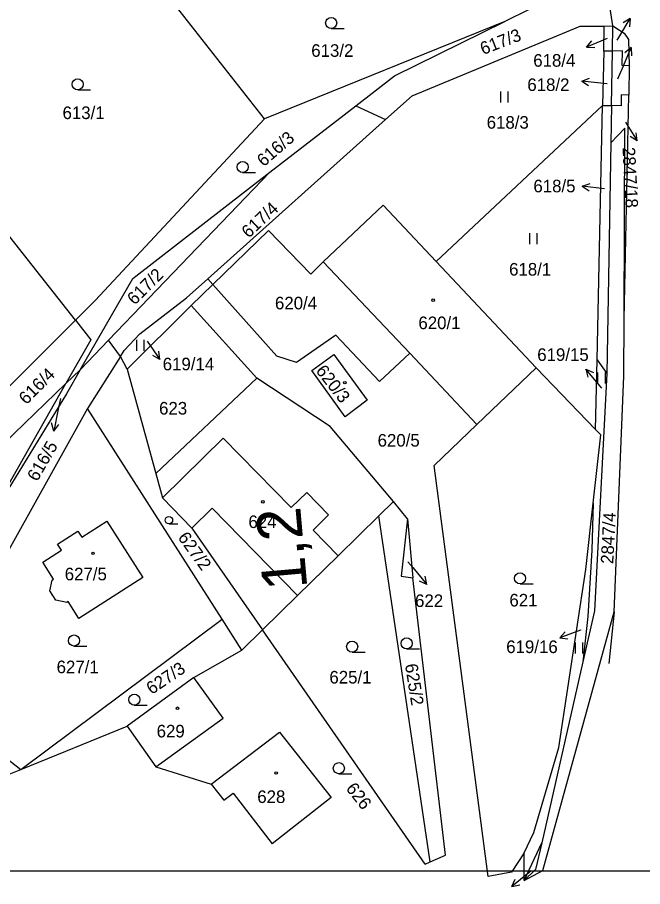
# Model space of a CAD drawing. Extents: x -558358 to -557517, y -1073786 to -1073189.
# Drawn here: x -558268.9 to -558184.5, y -1073786.2 to -1073668.8 of the extents above; entities that cross this region are included whole.
import ezdxf

# ---------------------------------------------------------------- set-up
doc = ezdxf.new("R2010")
doc.units = 0
for name, color, linetype in [('Hranice parcel', 7, 'Continuous'), ('Návěst místo trati', 7, 'Continuous'), ('Parcelní čísla', 7, 'Continuous'), ('Pop  PČ popisy', 7, 'Continuous'), ('Vnitřní kresba', 7, 'Continuous'), ('Vrstva 1', 7, 'Continuous'), ('Značky budov', 7, 'Continuous'), ('Značky kultur', 7, 'Continuous')]:
    doc.layers.add(name, color=color, linetype=linetype)

msp = doc.modelspace()

# ---------------------------------------------------------------- linework, layer by layer
at = {"layer": 'Hranice parcel'}
for p, q in [((-558235.56, -1073682.51), (-558250.61, -1073663.38)), ((-558188.53, -1073669.97), (-558189.35, -1073664.58)), ((-558196.23, -1073665.95), (-558203.14, -1073669.36)), ((-558203.14, -1073669.36), (-558235.56, -1073682.51)), ((-558189.77, -1073673.37), (-558189.69, -1073669.98)), ((-558189.69, -1073669.98), (-558188.53, -1073669.97)), ((-558188.59, -1073673.36), (-558188.53, -1073669.97)), ((-558188.53, -1073669.97), (-558186.98, -1073670.93)), ((-558189.77, -1073673.37), (-558189.93, -1073680.69)), ((-558188.59, -1073673.36), (-558189.77, -1073673.37)), ((-558188.72, -1073680.72), (-558188.59, -1073673.36)), ((-558187.23, -1073673.34), (-558188.59, -1073673.36)), ((-558186.31, -1073675.34), (-558186.36, -1073679.31)), ((-558261.12, -1073709.7), (-558287.25, -1073676.53)), ((-558187.01, -1073709.55), (-558186.36, -1073679.31)), ((-558234.84, -1073689.73), (-558223.26, -1073680.77)), ((-558223.26, -1073680.77), (-558219.23, -1073682.6)), ((-558189.93, -1073680.69), (-558212.4, -1073701.75)), ((-558190.64, -1073715.05), (-558189.93, -1073680.69)), ((-558189.93, -1073680.69), (-558188.72, -1073680.72)), ((-558188.72, -1073680.72), (-558188.81, -1073685.75)), ((-558187.4, -1073680.75), (-558188.72, -1073680.72)), ((-558243.24, -1073704.13), (-558219.23, -1073682.6)), ((-558186.92, -1073683.79), (-558188.81, -1073685.75)), ((-558187.01, -1073709.55), (-558186.92, -1073683.79)), ((-558188.81, -1073685.75), (-558189.35, -1073716.89)), ((-558256.63, -1073712.41), (-558234.84, -1073689.73)), ((-558227.63, -1073701.8), (-558215.96, -1073714.16)), ((-558212.4, -1073701.75), (-558198.87, -1073716.11)), ((-558245.46, -1073707.69), (-558242.57, -1073704.88)), ((-558242.57, -1073704.88), (-558243.24, -1073704.13)), ((-558233.91, -1073714.56), (-558242.57, -1073704.88)), ((-558245.46, -1073707.69), (-558254.11, -1073716.3)), ((-558236.6, -1073717.53), (-558245.46, -1073707.69)), ((-558256.63, -1073712.41), (-558260.45, -1073716.38)), ((-558255.01, -1073714.6), (-558256.63, -1073712.41)), ((-558206.91, -1073723.76), (-558215.96, -1073714.16)), ((-558255.01, -1073714.6), (-558259.48, -1073721.62)), ((-558254.11, -1073716.3), (-558255.01, -1073714.6)), ((-558190.86, -1073724.46), (-558190.64, -1073715.05)), ((-558190.64, -1073715.05), (-558189.35, -1073716.89)), ((-558262.39, -1073718.25), (-558260.45, -1073716.38)), ((-558254.11, -1073716.3), (-558250.26, -1073730.4)), ((-558198.87, -1073716.11), (-558206.91, -1073723.76)), ((-558190.86, -1073724.46), (-558198.87, -1073716.11)), ((-558250.26, -1073730.4), (-558236.6, -1073717.53)), ((-558226.69, -1073724.03), (-558236.6, -1073717.53)), ((-558274.72, -1073739.9), (-558262.39, -1073718.25)), ((-558259.48, -1073721.62), (-558281.15, -1073760.49)), ((-558241.29, -1073750.06), (-558259.48, -1073721.62)), ((-558218.17, -1073734.19), (-558226.69, -1073724.03)), ((-558250.26, -1073730.4), (-558249.36, -1073733.68)), ((-558220.12, -1073736.1), (-558218.17, -1073734.19)), ((-558216.24, -1073736.49), (-558218.17, -1073734.19)), ((-558191.18, -1073734.38), (-558191.35, -1073740.76)), ((-558213.21, -1073782.82), (-558220.12, -1073736.1)), ((-558216.24, -1073736.49), (-558215.54, -1073744.47)), ((-558191.35, -1073740.76), (-558191.89, -1073749.68)), ((-558191.89, -1073749.68), (-558192.59, -1073755.8)), ((-558188.37, -1073749.08), (-558189.08, -1073756.06)), ((-558268.5, -1073770.34), (-558241.29, -1073750.06)), ((-558238.63, -1073754.22), (-558241.29, -1073750.06)), ((-558235.84, -1073751.49), (-558238.63, -1073754.22)), ((-558213.89, -1073783.12), (-558235.84, -1073751.49)), ((-558245.1, -1073757.92), (-558238.63, -1073754.22)), ((-558192.59, -1073755.8), (-558198.14, -1073780.25)), ((-558245.1, -1073757.92), (-558254.1, -1073764.51)), ((-558281.15, -1073760.49), (-558268.5, -1073770.34)), ((-558268.5, -1073770.34), (-558254.1, -1073764.51)), ((-558254.1, -1073764.51), (-558250.25, -1073769.98)), ((-558279.1, -1073774.62), (-558268.5, -1073770.34)), ((-558250.25, -1073769.98), (-558242.76, -1073772.31)), ((-558200.51, -1073785.33), (-558198.14, -1073780.25)), ((-558200.51, -1073785.33), (-558200.5, -1073781.61)), ((-558213.89, -1073783.12), (-558213.21, -1073782.82))]:
    msp.add_line(p, q, dxfattribs=at)
for points in [[(-558223.26, -1073680.77), (-558218.03, -1073676.72), (-558203.14, -1073669.36)], [(-558219.23, -1073682.6), (-558215.65, -1073679.39), (-558192.95, -1073670.01), (-558189.69, -1073669.98)], [(-558186.98, -1073670.93), (-558186.43, -1073671.79), (-558186.31, -1073675.34)], [(-558186.31, -1073675.34), (-558187.29, -1073675.33), (-558187.23, -1073673.34)], [(-558186.36, -1073679.31), (-558187.4, -1073679.28), (-558187.4, -1073680.75)], [(-558235.56, -1073682.51), (-558258.46, -1073707.03), (-558261.12, -1073709.7)], [(-558260.45, -1073716.38), (-558253.37, -1073704.07), (-558234.84, -1073689.73)], [(-558227.63, -1073701.8), (-558219.54, -1073694.18), (-558212.4, -1073701.75)], [(-558242.57, -1073704.88), (-558235.04, -1073697.59), (-558229.33, -1073703.46), (-558227.63, -1073701.8)], [(-558255.01, -1073714.6), (-558254.51, -1073713.78), (-558252.39, -1073711.53), (-558246.1, -1073706.69), (-558243.24, -1073704.13)], [(-558289.37, -1073741.07), (-558281.4, -1073729.91), (-558261.12, -1073709.7)], [(-558261.12, -1073709.7), (-558259.03, -1073712.35), (-558262.39, -1073718.25)], [(-558188.37, -1073749.08), (-558187.04, -1073717.25), (-558187.01, -1073709.55)], [(-558215.96, -1073714.16), (-558220.05, -1073717.99), (-558225.94, -1073711.71), (-558231.23, -1073715.41), (-558233.91, -1073714.56)], [(-558224.7, -1073722.72), (-558229.2, -1073716.48), (-558226.19, -1073714.33), (-558221.69, -1073720.48), (-558224.7, -1073722.72)], [(-558260.45, -1073716.38), (-558262.32, -1073719.63), (-558274.72, -1073739.9)], [(-558189.35, -1073716.89), (-558191.03, -1073748.95), (-558192.59, -1073755.8)], [(-558262.39, -1073718.25), (-558277.79, -1073733.11), (-558288.61, -1073748.35)], [(-558200.5, -1073781.61), (-558202.2, -1073784.23), (-558205.35, -1073784.79), (-558212.68, -1073729.29), (-558206.91, -1073723.76)], [(-558191.18, -1073734.38), (-558190.17, -1073725.16), (-558190.86, -1073724.46)], [(-558249.36, -1073733.68), (-558245.38, -1073737.75), (-558235.84, -1073751.49)], [(-558200.5, -1073781.61), (-558199.18, -1073778.85), (-558195.83, -1073767.37), (-558192.17, -1073743.33), (-558191.18, -1073734.38)], [(-558235.84, -1073751.49), (-558231.13, -1073746.88), (-558225.62, -1073741.49), (-558220.12, -1073736.1)], [(-558216.24, -1073736.49), (-558217.14, -1073744.24), (-558215.54, -1073744.47)], [(-558264.25, -1073744.77), (-558264.05, -1073744.64), (-558265.49, -1073742.37), (-558262.97, -1073740.76), (-558263.51, -1073739.92), (-558260.77, -1073738.16), (-558260.22, -1073739), (-558256.85, -1073736.83), (-558251.99, -1073744.42), (-558260.65, -1073749.95), (-558262.08, -1073747.68), (-558262.29, -1073747.81), (-558263.76, -1073747.5), (-558264.56, -1073746.23), (-558264.25, -1073744.77)], [(-558213.21, -1073782.82), (-558211.14, -1073781.9), (-558215.54, -1073744.47)], [(-558200.51, -1073785.33), (-558197.97, -1073783.99), (-558188.37, -1073749.08)], [(-558250.25, -1073769.98), (-558241.14, -1073763.44), (-558245.1, -1073757.92)], [(-558242.76, -1073772.31), (-558233.55, -1073765.31), (-558226.57, -1073774.11), (-558234.56, -1073780.4)], [(-558242.76, -1073772.31), (-558241.08, -1073774.51), (-558239.8, -1073773.53), (-558234.56, -1073780.4)], [(-558198.14, -1073780.25), (-558198.96, -1073783.85), (-558200.51, -1073785.33)]]:
    msp.add_lwpolyline(points, dxfattribs=at)
at = {"layer": 'Pop  PČ popisy'}
for p, q in [((-558187.72, -1073671.53), (-558186.17, -1073668.96)), ((-558186.17, -1073668.96), (-558187.12, -1073669.56)), ((-558186.17, -1073668.96), (-558186.26, -1073670.07)), ((-558189.32, -1073671.65), (-558192.08, -1073672.82)), ((-558192.08, -1073672.82), (-558191.36, -1073671.97)), ((-558187.93, -1073671.89), (-558187.72, -1073671.53)), ((-558192.08, -1073672.82), (-558190.96, -1073672.89)), ((-558187.24, -1073675.66), (-558186.07, -1073672.9)), ((-558186.07, -1073672.9), (-558186.92, -1073673.62)), ((-558186.07, -1073672.9), (-558186, -1073674.02)), ((-558187.86, -1073677.09), (-558187.24, -1073675.66)), ((-558192.74, -1073677.42), (-558191.7, -1073677.02)), ((-558189.76, -1073677.73), (-558192.74, -1073677.42)), ((-558192.74, -1073677.42), (-558191.8, -1073678.02)), ((-558189.29, -1073677.78), (-558189.76, -1073677.73)), ((-558186.84, -1073682.95), (-558185.25, -1073685.5)), ((-558185.25, -1073685.5), (-558186.2, -1073684.91)), ((-558185.25, -1073685.5), (-558185.36, -1073684.38)), ((-558192.66, -1073691.6), (-558191.6, -1073691.23)), ((-558189.68, -1073691.97), (-558192.66, -1073691.6)), ((-558192.66, -1073691.6), (-558191.73, -1073692.22)), ((-558251.41, -1073712.52), (-558249.69, -1073714.98)), ((-558249.69, -1073714.98), (-558250.67, -1073714.45)), ((-558249.69, -1073714.98), (-558249.85, -1073713.87)), ((-558190.25, -1073718.6), (-558192.18, -1073716.3)), ((-558192.18, -1073716.3), (-558191.15, -1073716.75)), ((-558192.18, -1073716.3), (-558191.92, -1073717.39)), ((-558190.03, -1073718.86), (-558190.25, -1073718.6)), ((-558263.11, -1073720.25), (-558263.42, -1073721.72)), ((-558263.42, -1073721.72), (-558264.04, -1073724.66)), ((-558264.04, -1073724.66), (-558264.33, -1073723.57)), ((-558264.04, -1073724.66), (-558263.35, -1073723.78)), ((-558216.21, -1073742.3), (-558215.56, -1073743.06)), ((-558215.56, -1073743.06), (-558213.63, -1073745.36)), ((-558213.63, -1073745.36), (-558214.66, -1073744.91)), ((-558213.63, -1073745.36), (-558213.89, -1073744.27)), ((-558192.9, -1073751.52), (-558195.7, -1073752.59)), ((-558195.7, -1073752.59), (-558194.95, -1073751.77)), ((-558192.88, -1073751.51), (-558192.9, -1073751.52)), ((-558195.7, -1073752.59), (-558194.59, -1073752.7)), ((-558199.85, -1073784.27), (-558202.18, -1073786.16)), ((-558199.56, -1073784.03), (-558199.85, -1073784.27)), ((-558202.18, -1073786.16), (-558201.72, -1073785.14)), ((-558202.18, -1073786.16), (-558201.09, -1073785.92))]:
    msp.add_line(p, q, dxfattribs=at)
at = {"layer": 'Vnitřní kresba'}
for p, q in [((-558249.36, -1073733.68), (-558241.14, -1073725.64)), ((-558241.14, -1073725.64), (-558231.97, -1073735)), ((-558231.97, -1073735), (-558229.86, -1073732.94)), ((-558229.86, -1073732.94), (-558226.91, -1073735.96)), ((-558245.38, -1073737.75), (-558242.66, -1073735.09)), ((-558242.66, -1073735.09), (-558231.13, -1073746.88)), ((-558229.02, -1073738.02), (-558226.91, -1073735.96)), ((-558229.02, -1073738.02), (-558225.62, -1073741.49))]:
    msp.add_line(p, q, dxfattribs=at)
at = {"layer": 'Vrstva 1'}
msp.add_line((-557516.53, -1073784.09), (-558357.53, -1073784.09), dxfattribs=at)
at = {"layer": 'Značky budov'}
for centre in [(-558212.8, -1073706.99), (-558224.72, -1073718.13), (-558235.8, -1073734.21), (-558258.73, -1073741.17), (-558247.32, -1073762.08), (-558233.99, -1073770.82)]:
    msp.add_circle(centre, 0.175, dxfattribs=at)
at = {"layer": 'Značky kultur'}
for p, q in [((-558226.57, -1073670.32), (-558224.82, -1073670.32)), ((-558260.8, -1073678.6), (-558259.05, -1073678.6)), ((-558203.68, -1073680.3), (-558203.68, -1073678.8)), ((-558202.68, -1073680.3), (-558202.68, -1073678.8)), ((-558238.53, -1073689.76), (-558236.78, -1073689.76)), ((-558199.75, -1073699.45), (-558199.75, -1073697.95)), ((-558198.75, -1073699.45), (-558198.75, -1073697.95)), ((-558252.83, -1073713.85), (-558252.83, -1073712.35)), ((-558251.83, -1073713.85), (-558251.83, -1073712.35)), ((-558190.54, -1073718.24), (-558190.54, -1073716.74)), ((-558189.54, -1073718.24), (-558189.54, -1073716.74)), ((-558248.47, -1073737.19), (-558247.3, -1073737.19)), ((-558201.06, -1073745.3), (-558199.31, -1073745.3)), ((-558193.57, -1073754.69), (-558193.57, -1073753.19)), ((-558192.57, -1073754.69), (-558192.57, -1073753.19)), ((-558261.31, -1073753.69), (-558259.56, -1073753.69)), ((-558216.38, -1073754.08), (-558214.63, -1073754.08)), ((-558223.74, -1073754.51), (-558221.99, -1073754.51)), ((-558253.16, -1073761.67), (-558251.41, -1073761.67)), ((-558225.53, -1073770.92), (-558223.78, -1073770.92))]:
    msp.add_line(p, q, dxfattribs=at)
for centre, radius in [((-558226.57, -1073669.57), 0.75), ((-558260.8, -1073677.85), 0.75), ((-558238.53, -1073689.01), 0.75), ((-558248.48, -1073736.69), 0.502), ((-558201.06, -1073744.55), 0.75), ((-558261.3, -1073752.94), 0.75), ((-558223.74, -1073753.76), 0.75), ((-558216.38, -1073753.33), 0.75), ((-558253.16, -1073760.92), 0.75), ((-558225.53, -1073770.17), 0.75)]:
    msp.add_circle(centre, radius, dxfattribs=at)

# ---------------------------------------------------------------- texts
at = {"layer": 'Návěst místo trati'}
msp.add_text('1,2', height=6, rotation=95.054, dxfattribs=at).set_placement((-558229.78, -1073745.86))
at = {"layer": 'Parcelní čísla'}
for s, rotation, p in [('617/3', 21, (-558206.06, -1073673.9)), ('616/3', 41, (-558235.68, -1073689.06)), ('2847/18', 273, (-558187.23, -1073686.37)), ('617/4', 43, (-558237.71, -1073698.7)), ('617/2', 45, (-558253.11, -1073707.74)), ('616/4', 45, (-558267.74, -1073721.18)), ('620/3', 308, (-558228.73, -1073716.55)), ('616/5', 60, (-558266.27, -1073731.57)), ('2847/4', 87, (-558188.48, -1073742.63)), ('627/2', 306, (-558247.35, -1073739.04)), ('627/3', 34, (-558250.81, -1073760.3)), ('625/2', 279, (-558216.61, -1073756.19)), ('626', 308, (-558224.66, -1073772.94))]:
    msp.add_text(s, height=1.7, rotation=rotation, dxfattribs=at).set_placement(p)
for s, p in [('613/2', (-558229.26, -1073674.14)), ('618/4', (-558199.28, -1073675.47)), ('618/2', (-558200.08, -1073678.75)), ('613/1', (-558262.85, -1073682.54)), ('618/3', (-558205.57, -1073683.84)), ('618/5', (-558199.26, -1073692.43)), ('618/1', (-558202.54, -1073703.67)), ('620/4', (-558234.16, -1073708.23)), ('620/1', (-558214.79, -1073710.9)), ('619/15', (-558198.74, -1073715.19)), ('619/14', (-558249.32, -1073716.46)), ('623', (-558249.81, -1073722.43)), ('620/5', (-558220.3, -1073726.76)), ('624', (-558237.74, -1073737.75)), ('627/5', (-558262.55, -1073744.81)), ('622', (-558215.24, -1073748.41)), ('621', (-558202.5, -1073748.34)), ('619/16', (-558202.93, -1073754.63)), ('627/1', (-558263.65, -1073757.35)), ('625/1', (-558226.81, -1073758.74)), ('629', (-558250.14, -1073766.02)), ('628', (-558236.55, -1073774.87))]:
    msp.add_text(s, height=1.7, dxfattribs=at).set_placement(p)

doc.saveas('drawing.dxf')
